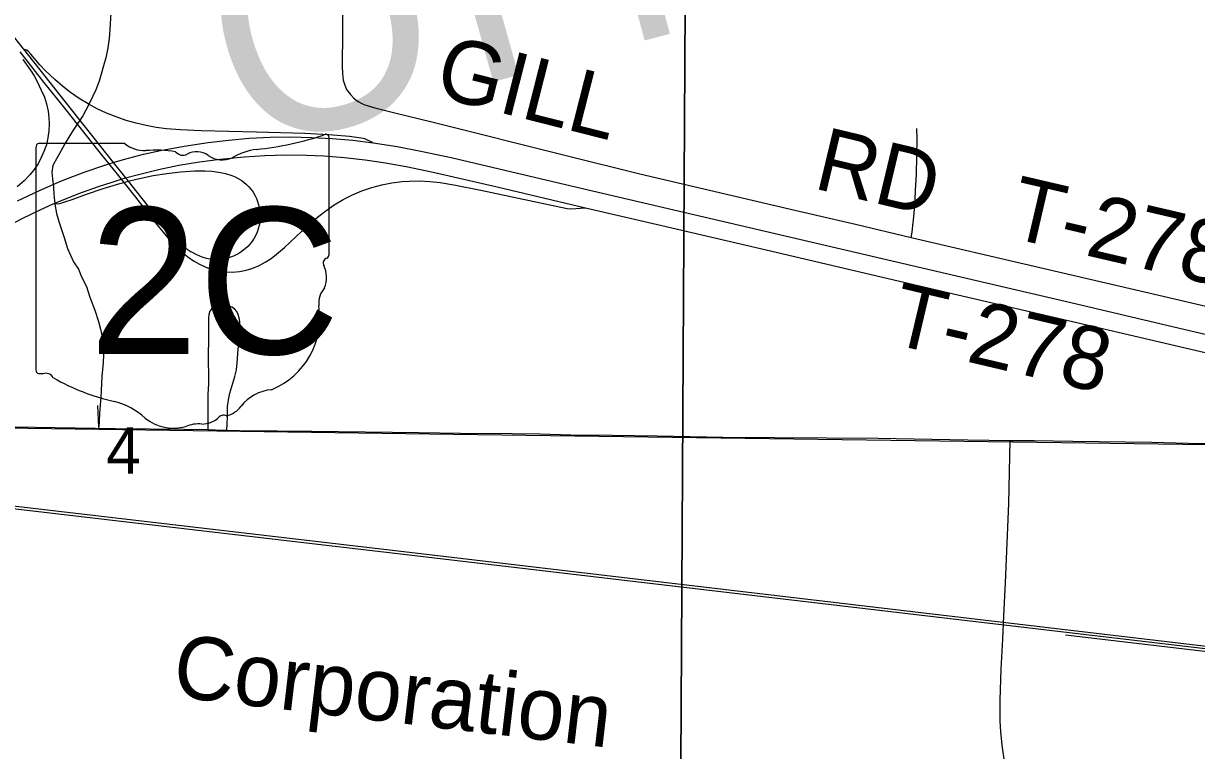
# Model space of a CAD drawing. Extents: x 0 to 34, y 0 to 22.
# Drawn here: x 4.496 to 5.024, y 18.052 to 18.379 of the extents above; entities that cross this region are included whole.
import ezdxf

# ---------------------------------------------------------------- set-up
doc = ezdxf.new("R2010")
doc.units = 0
for name, color, linetype in [('GM_X_Corporation', 7, 'Continuous'), ('GM_X_County_Road', 7, 'Continuous'), ('GM_X_County_Text', 7, 'Continuous'), ('GM_X_Interchange_Ramps', 7, 'Continuous'), ('GM_X_Minor_River', 7, 'Continuous'), ('GM_X_Rail_Line', 7, 'Continuous'), ('GM_X_Rail_Line_Text', 7, 'Continuous'), ('GM_X_Section_Text', 7, 'Continuous'), ('GM_X_State_Location', 7, 'Continuous'), ('GM_X_State_Route', 7, 'Continuous'), ('GM_X_State_Shield', 7, 'Continuous'), ('GM_X_Township_Road', 7, 'Continuous'), ('GM_X_Township_Road_Text', 7, 'Continuous')]:
    doc.layers.add(name, color=color, linetype=linetype)

msp = doc.modelspace()

# ---------------------------------------------------------------- linework, layer by layer
at = {"layer": 'GM_X_Corporation'}
for points in [[(4.7863140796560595, 18.439525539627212), (4.793706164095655, 18.439490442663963), (4.790900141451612, 17.9408439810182), (4.28638989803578, 17.945190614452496), (4.2929909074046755, 18.446469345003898)], [(5.290701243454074, 18.432879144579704), (5.304818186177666, 18.432612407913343), (5.3004127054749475, 17.936980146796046), (5.298641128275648, 17.936856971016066), (4.790900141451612, 17.9408439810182), (4.793706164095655, 18.439490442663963)]]:
    msp.add_lwpolyline(points, close=True, dxfattribs=at)
at = {"layer": 'GM_X_County_Road'}
for points in [[(4.483977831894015, 18.197444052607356), (4.492080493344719, 18.19733221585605), (4.537108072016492, 18.19660519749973), (4.568167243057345, 18.196278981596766), (4.578718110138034, 18.19613296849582)], [(4.578718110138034, 18.19613296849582), (4.58213252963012, 18.196083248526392), (4.587320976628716, 18.195921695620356), (4.592994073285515, 18.19574461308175), (4.610081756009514, 18.195670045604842), (4.625600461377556, 18.195433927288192), (4.673741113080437, 18.19481254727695), (4.692379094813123, 18.194598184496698), (4.715671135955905, 18.194386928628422), (4.72808302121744, 18.1941942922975), (4.742048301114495, 18.193781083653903), (4.760689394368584, 18.19364127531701), (4.780874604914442, 18.19340825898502), (4.810371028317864, 18.19281174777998), (4.880259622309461, 18.192227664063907), (4.920630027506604, 18.191513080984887), (4.939625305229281, 18.191252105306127)], [(4.939625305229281, 18.191252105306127), (4.950396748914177, 18.19122724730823), (4.9679162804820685, 18.190916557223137), (5.00338407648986, 18.19043811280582), (5.025197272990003, 18.189950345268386), (5.040771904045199, 18.189885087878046), (5.046985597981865, 18.19004665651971), (5.053180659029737, 18.190475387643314), (5.0593415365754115, 18.19122102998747), (5.0654527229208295, 18.192305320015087), (5.071504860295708, 18.193694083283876), (5.074114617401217, 18.19440554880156), (5.076320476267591, 18.19516363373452)], [(4.936359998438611, 18.10180434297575), (4.936881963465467, 18.11227598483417), (4.937624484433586, 18.1271671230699), (4.939140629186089, 18.16289587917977), (4.939625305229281, 18.191252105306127)], [(4.946479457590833, 18.005246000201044), (4.944108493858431, 18.01443197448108), (4.941110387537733, 18.026523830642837), (4.938820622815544, 18.037183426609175), (4.9374380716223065, 18.044848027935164), (4.936083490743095, 18.054097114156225), (4.93546213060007, 18.060310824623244), (4.935235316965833, 18.064986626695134), (4.935222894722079, 18.07434133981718), (4.935688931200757, 18.08834080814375), (4.936359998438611, 18.10180434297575)]]:
    msp.add_lwpolyline(points, dxfattribs=at)
at = {"layer": 'GM_X_Interchange_Ramps'}
for points in [[(4.653189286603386, 18.325238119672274), (4.649454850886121, 18.327002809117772), (4.647739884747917, 18.327341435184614), (4.642557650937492, 18.32798145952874), (4.633258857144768, 18.328789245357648), (4.622387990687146, 18.329373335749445), (4.600621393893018, 18.329991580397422), (4.575738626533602, 18.330597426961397), (4.566414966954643, 18.331019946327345), (4.560216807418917, 18.331557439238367), (4.555590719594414, 18.332169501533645), (4.5510018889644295, 18.33298969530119), (4.5464565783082, 18.334036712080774), (4.541973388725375, 18.33531982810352), (4.537564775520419, 18.33684530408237), (4.53324313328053, 18.338600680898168), (4.529014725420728, 18.340573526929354), (4.524891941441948, 18.342760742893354), (4.52089342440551, 18.345165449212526), (4.516969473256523, 18.347918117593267), (4.513346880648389, 18.350763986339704), (4.510016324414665, 18.353755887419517), (4.505719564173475, 18.357667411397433), (4.503255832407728, 18.360320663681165), (4.499101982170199, 18.365102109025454), (4.497890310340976, 18.36639453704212), (4.497268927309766, 18.366935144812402), (4.495833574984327, 18.36737009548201)], [(4.495591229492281, 18.36263215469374), (4.499586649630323, 18.357039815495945), (4.500795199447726, 18.355057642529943), (4.501954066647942, 18.352789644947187), (4.503836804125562, 18.348927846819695), (4.505287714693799, 18.345693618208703), (4.506229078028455, 18.342726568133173), (4.5069654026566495, 18.339479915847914), (4.5073164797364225, 18.33661849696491), (4.507363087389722, 18.333576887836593), (4.507170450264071, 18.33053528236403), (4.506785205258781, 18.32739736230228), (4.506157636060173, 18.324306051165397), (4.505048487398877, 18.321264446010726), (4.503793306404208, 18.31856147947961), (4.502395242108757, 18.31576220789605), (4.5006554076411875, 18.31315246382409), (4.498676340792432, 18.310738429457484), (4.496119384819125, 18.308131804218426), (4.492934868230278, 18.30542882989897)], [(4.509140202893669, 18.297680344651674), (4.512144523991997, 18.2978853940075), (4.514039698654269, 18.298472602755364), (4.517702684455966, 18.299715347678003), (4.524239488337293, 18.30207033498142), (4.5316835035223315, 18.304661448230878), (4.539111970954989, 18.30694497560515), (4.540920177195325, 18.30742965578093), (4.542914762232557, 18.307942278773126), (4.54663366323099, 18.30888675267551), (4.55424233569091, 18.31047124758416), (4.560378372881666, 18.311434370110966), (4.566539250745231, 18.312161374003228), (4.572737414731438, 18.312531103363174), (4.577397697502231, 18.312549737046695), (4.580507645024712, 18.312403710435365), (4.583602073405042, 18.312055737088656), (4.586643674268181, 18.31144680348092), (4.589595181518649, 18.310511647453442), (4.591030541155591, 18.309899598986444), (4.5924131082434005, 18.309206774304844), (4.593736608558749, 18.30839587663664), (4.594994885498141, 18.30749798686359), (4.596172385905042, 18.306491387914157), (4.597262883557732, 18.30539155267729), (4.5982539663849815, 18.304201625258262), (4.599145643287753, 18.302934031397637), (4.599934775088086, 18.30160118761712), (4.600605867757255, 18.300200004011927), (4.601174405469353, 18.298752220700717), (4.601621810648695, 18.297264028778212), (4.601957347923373, 18.295747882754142), (4.602168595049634, 18.294209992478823), (4.602264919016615, 18.292659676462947), (4.602236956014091, 18.29110935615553), (4.6020878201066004, 18.28956215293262), (4.601817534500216, 18.288033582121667), (4.6014291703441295, 18.286532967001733), (4.600910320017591, 18.285069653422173), (4.600288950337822, 18.283646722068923), (4.599546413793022, 18.2822859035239), (4.598707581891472, 18.28098102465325), (4.597769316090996, 18.279744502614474), (4.596725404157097, 18.278594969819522), (4.59560071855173, 18.277526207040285), (4.594389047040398, 18.276556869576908), (4.5931059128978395, 18.275680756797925), (4.591754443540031, 18.274919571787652), (4.590353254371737, 18.274254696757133), (4.588899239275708, 18.27371099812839), (4.587407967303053, 18.273282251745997), (4.585888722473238, 18.272974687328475), (4.584350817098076, 18.272785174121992), (4.582803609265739, 18.272710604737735), (4.581253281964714, 18.272757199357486), (4.579709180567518, 18.272918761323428), (4.578189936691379, 18.273217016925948), (4.576692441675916, 18.27362401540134), (4.575235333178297, 18.274136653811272), (4.573803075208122, 18.274742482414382), (4.571239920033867, 18.276115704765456)]]:
    msp.add_lwpolyline(points, dxfattribs=at)
at = {"layer": 'GM_X_Minor_River'}
msp.add_lwpolyline([(4.535069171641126, 18.383743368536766), (4.534727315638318, 18.3761392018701), (4.534368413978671, 18.37214677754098), (4.5338201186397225, 18.367963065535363), (4.53289492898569, 18.36339867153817), (4.531774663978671, 18.35978124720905), (4.530843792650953, 18.356166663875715), (4.529910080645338, 18.352931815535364), (4.5284119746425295, 18.3491231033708), (4.5269091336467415, 18.345885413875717), (4.525218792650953, 18.342456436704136), (4.522587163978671, 18.337313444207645), (4.520324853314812, 18.334071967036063), (4.518253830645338, 18.330831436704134), (4.516181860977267, 18.32778124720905), (4.51448867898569, 18.3247329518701), (4.512606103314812, 18.321493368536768), (4.510725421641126, 18.31806249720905), (4.509032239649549, 18.3150142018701), (4.508668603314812, 18.311971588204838), (4.508873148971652, 18.308931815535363), (4.509271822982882, 18.305322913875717), (4.509478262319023, 18.302092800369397), (4.50988072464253, 18.297534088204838), (4.51066197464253, 18.29335605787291), (4.511821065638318, 18.28937120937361), (4.512976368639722, 18.28614583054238), (4.514133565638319, 18.282540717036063), (4.515677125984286, 18.277607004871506), (4.518365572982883, 18.271728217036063), (4.520661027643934, 18.26831723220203), (4.522006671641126, 18.26490245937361), (4.5241174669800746, 18.260541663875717), (4.525660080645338, 18.25579734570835), (4.527967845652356, 18.249916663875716), (4.529513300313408, 18.244792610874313), (4.53047920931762, 18.241375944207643), (4.531256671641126, 18.237959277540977), (4.531844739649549, 18.234351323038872), (4.531869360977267, 18.229600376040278), (4.531695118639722, 18.22636931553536), (4.531331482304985, 18.22313636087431), (4.531158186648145, 18.220094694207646), (4.530984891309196, 18.216863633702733), (4.530809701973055, 18.213821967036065), (4.530636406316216, 18.210780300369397), (4.5302756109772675, 18.20697727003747), (4.53010420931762, 18.203366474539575), (4.529930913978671, 18.200134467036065), (4.529756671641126, 18.197092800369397), (4.5293267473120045, 18.20697348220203)], dxfattribs=at)
at = {"layer": 'GM_X_Rail_Line'}
for points in [[(4.40206186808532, 18.198089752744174), (4.689172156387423, 18.194089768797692), (5.00634961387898, 18.189760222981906), (5.158754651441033, 18.18759547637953), (5.362477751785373, 18.182647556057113), (5.718297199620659, 18.179555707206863), (5.931912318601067, 18.177082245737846), (6.251871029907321, 18.271402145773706), (6.499490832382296, 18.346858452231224), (7.043266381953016, 18.517872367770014), (7.079127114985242, 18.527767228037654), (7.128898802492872, 18.529932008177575), (7.241734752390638, 18.536426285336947), (7.289651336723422, 18.563330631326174), (7.338185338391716, 18.597657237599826)], [(4.301188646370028, 18.184044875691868), (4.669435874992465, 18.14102596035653), (5.180445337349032, 18.08076212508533), (5.377502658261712, 18.058353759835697), (5.425517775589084, 18.05195899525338), (5.449742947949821, 18.049302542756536), (5.589237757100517, 18.032723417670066), (5.690295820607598, 18.020904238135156), (5.758989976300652, 18.012773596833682), (5.8874553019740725, 17.99778132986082), (5.939531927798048, 17.991554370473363), (5.980265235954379, 17.98675519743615), (5.999674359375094, 17.984413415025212), (6.017423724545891, 17.981872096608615)], [(4.301053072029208, 18.18289140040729), (4.669299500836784, 18.139872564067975), (5.1803107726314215, 18.079608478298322), (5.377359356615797, 18.05720110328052), (5.42537678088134, 18.050806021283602), (5.449610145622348, 18.048148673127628), (5.589100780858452, 18.03157003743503), (5.690159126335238, 18.019750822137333), (5.758853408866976, 18.01162014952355), (5.887318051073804, 17.996627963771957), (5.9393940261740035, 17.99040107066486), (5.980126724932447, 17.985601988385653), (5.999521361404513, 17.983261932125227), (6.017250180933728, 17.98072357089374)], [(4.964565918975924, 18.10386820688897), (5.1801762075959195, 18.078454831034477), (5.36393862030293, 18.057557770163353)]]:
    msp.add_lwpolyline(points, dxfattribs=at)
at = {"layer": 'GM_X_State_Route'}
for points in [[(4.488529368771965, 18.376684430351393), (4.495143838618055, 18.368236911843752), (4.495833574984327, 18.36737009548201), (4.517301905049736, 18.340225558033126), (4.5362474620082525, 18.316315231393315), (4.541731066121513, 18.309402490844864), (4.542914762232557, 18.307942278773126), (4.552993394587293, 18.295250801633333), (4.560810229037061, 18.285597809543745), (4.563910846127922, 18.28211814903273), (4.566135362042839, 18.27994956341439), (4.5685120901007, 18.277961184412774), (4.571239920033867, 18.276115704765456)], [(4.494267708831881, 18.366105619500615), (4.504899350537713, 18.35250072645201), (4.51421991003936, 18.340818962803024), (4.5298100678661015, 18.3213763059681), (4.531006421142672, 18.31987174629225)], [(4.493158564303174, 18.299103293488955), (4.502997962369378, 18.30372938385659), (4.512961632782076, 18.308075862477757), (4.523096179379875, 18.312012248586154), (4.5319258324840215, 18.315016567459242), (4.534296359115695, 18.315734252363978), (4.5362474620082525, 18.316315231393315), (4.540858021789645, 18.317688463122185), (4.549886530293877, 18.320034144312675), (4.557467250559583, 18.32170563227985), (4.568151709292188, 18.323709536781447), (4.57890139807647, 18.325346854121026), (4.588150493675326, 18.32645288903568), (4.597430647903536, 18.327232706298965), (4.60673566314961, 18.327686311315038), (4.616050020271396, 18.32783544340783), (4.625367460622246, 18.32767699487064), (4.6346693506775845, 18.32721406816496), (4.643946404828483, 18.32639695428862), (4.653189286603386, 18.325238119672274), (4.6639234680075, 18.3235231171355), (4.674607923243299, 18.32149434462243), (4.688278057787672, 18.31853973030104), (4.747339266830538, 18.304723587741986), (4.7973036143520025, 18.292992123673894), (4.886662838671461, 18.272126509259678), (4.96690966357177, 18.253289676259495), (5.018399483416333, 18.2412351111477), (5.056253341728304, 18.232368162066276)], [(4.531006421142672, 18.31987174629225), (4.534296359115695, 18.315734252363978), (4.539758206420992, 18.308852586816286), (4.540920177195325, 18.30742965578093), (4.5462546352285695, 18.300715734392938), (4.555789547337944, 18.28845300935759), (4.560763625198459, 18.28248784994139), (4.563929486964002, 18.279067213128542), (4.5673190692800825, 18.275873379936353), (4.56973619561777, 18.273919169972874), (4.572286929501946, 18.27214515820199), (4.574980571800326, 18.27058240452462), (4.5777953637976, 18.269271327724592), (4.580712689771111, 18.268230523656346), (4.583729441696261, 18.267515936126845), (4.586808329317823, 18.267130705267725), (4.589912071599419, 18.26707476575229), (4.593003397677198, 18.267345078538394), (4.596048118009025, 18.267944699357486), (4.59901824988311, 18.268851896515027), (4.601882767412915, 18.27004181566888), (4.604616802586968, 18.271511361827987), (4.607201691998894, 18.273210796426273), (4.609684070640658, 18.275084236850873), (4.6132227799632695, 18.278128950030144), (4.623419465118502, 18.28771046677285), (4.6281263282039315, 18.29177113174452), (4.631807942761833, 18.294620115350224), (4.63566044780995, 18.297245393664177), (4.639662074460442, 18.299637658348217), (4.643809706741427, 18.301756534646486), (4.648097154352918, 18.30358337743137), (4.652499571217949, 18.30510882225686), (4.656998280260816, 18.30632670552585), (4.661568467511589, 18.307240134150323), (4.6661883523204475, 18.30782110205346), (4.669282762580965, 18.308023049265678), (4.673943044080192, 18.308082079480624), (4.678590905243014, 18.30782111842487), (4.683223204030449, 18.30731468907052), (4.689362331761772, 18.30634535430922), (4.701562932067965, 18.303949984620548), (4.740379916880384, 18.295719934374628), (4.742032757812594, 18.295570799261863), (4.748700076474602, 18.29602440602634)], [(4.535692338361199, 18.307579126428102), (4.538506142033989, 18.30847975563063), (4.539758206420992, 18.308852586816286), (4.541731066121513, 18.309402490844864), (4.54751912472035, 18.311014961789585), (4.556612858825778, 18.313230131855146), (4.565778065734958, 18.315119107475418), (4.574999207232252, 18.316678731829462), (4.584263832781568, 18.31791837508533), (4.595109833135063, 18.318962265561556), (4.604433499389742, 18.31953393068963), (4.613772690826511, 18.31976072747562), (4.623114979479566, 18.319667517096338), (4.6308945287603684, 18.319344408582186), (4.640208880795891, 18.318629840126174), (4.649492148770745, 18.317592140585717), (4.6587350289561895, 18.316256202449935), (4.667928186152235, 18.314603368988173), (4.680103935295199, 18.312027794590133), (4.708882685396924, 18.305372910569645), (4.748700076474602, 18.29602440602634)], [(4.509140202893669, 18.297680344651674), (4.512119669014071, 18.29901009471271), (4.520797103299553, 18.302477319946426), (4.529595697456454, 18.305627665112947), (4.535692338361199, 18.307579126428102)], [(4.444049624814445, 18.257789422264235), (4.450395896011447, 18.26299238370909), (4.459769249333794, 18.269936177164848), (4.470068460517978, 18.276883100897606), (4.477503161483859, 18.281285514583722), (4.48693554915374, 18.286738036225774), (4.495193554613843, 18.29110625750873), (4.503591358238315, 18.295197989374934), (4.509140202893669, 18.297680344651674)], [(4.748700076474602, 18.29602440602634), (4.783021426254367, 18.287965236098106), (4.829962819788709, 18.277097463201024), (4.911641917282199, 18.257803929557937), (4.976733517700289, 18.242654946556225), (5.111306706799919, 18.211222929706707), (5.120518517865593, 18.2090823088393), (5.193144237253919, 18.192028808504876), (5.345995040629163, 18.156290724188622), (5.42624185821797, 18.13749117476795), (5.439800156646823, 18.134315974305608), (5.569924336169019, 18.103903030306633), (5.586632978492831, 18.10032703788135), (5.595785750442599, 18.09861517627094), (5.604985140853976, 18.097186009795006), (5.6157659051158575, 18.09583452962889), (5.6265808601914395, 18.094778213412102), (5.637423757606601, 18.094035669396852), (5.6513859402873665, 18.09349817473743), (5.670474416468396, 18.093072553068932)]]:
    msp.add_lwpolyline(points, dxfattribs=at)
at = {"layer": 'GM_X_State_Shield'}
for p, q in [((4.6332900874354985, 18.275023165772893), (4.6332900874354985, 18.32736586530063)), ((4.501456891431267, 18.32316457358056), (4.501456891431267, 18.223104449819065)), ((4.541362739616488, 18.32488620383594), (4.50275453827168, 18.32488620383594)), ((4.633277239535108, 18.275036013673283), (4.6332900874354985, 18.275023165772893))]:
    msp.add_line(p, q, dxfattribs=at)
for centre, radius, start, end in [((4.5863291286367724, 18.461302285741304), 0.1398078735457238, 275.8444694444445, 288.9064527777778), ((4.631827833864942, 18.327582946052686), 0.0014676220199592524, 351.8620861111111, 97.738), ((4.502967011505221, 18.323377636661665), 0.001527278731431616, 98.1301027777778, 188.13010277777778), ((4.5505572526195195, 18.336502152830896), 0.014813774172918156, 231.61950555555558, 271.11188333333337), ((4.555468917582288, 18.26871131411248), 0.053181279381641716, 80.48669166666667, 94.98826944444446), ((4.567542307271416, 18.323896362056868), 0.00427366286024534, 219.79206111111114, 297.1023694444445), ((4.573816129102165, 18.312331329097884), 0.008885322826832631, 54.466683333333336, 119.14113055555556), ((4.604162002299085, 18.294324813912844), 0.028127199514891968, 97.34618055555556, 120.7688527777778), ((4.585284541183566, 18.328193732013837), 0.010688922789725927, 233.85620555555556, 294.82819166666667), ((4.632951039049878, 18.271180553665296), 0.002271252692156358, 107.94398333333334, 210.33696666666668), ((4.631724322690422, 18.274820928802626), 0.001570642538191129, 289.6038111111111, 7.734130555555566), ((4.618501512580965, 18.26456407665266), 0.013634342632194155, 340.0329638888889, 23.649566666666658), ((4.638548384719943, 18.253118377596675), 0.009919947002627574, 136.80649722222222, 186.92959444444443), ((4.594160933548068, 18.246459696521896), 0.03496914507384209, 292.3088861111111, 8.985838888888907), ((4.502980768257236, 18.222885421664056), 0.0015408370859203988, 171.9583861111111, 258.30661388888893), ((4.503214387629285, 18.233122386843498), 0.011758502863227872, 267.33899444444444, 280.6038555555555), ((4.505620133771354, 18.21733173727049), 0.00423985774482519, 29.748380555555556, 93.27174722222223), ((4.559150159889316, 18.30723159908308), 0.10096071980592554, 240.41292222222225, 257.1985), ((4.6089055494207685, 18.19501278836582), 0.01915169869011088, 94.40312222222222, 142.57675), ((4.529050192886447, 18.178152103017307), 0.031588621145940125, 47.184155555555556, 75.83597222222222), ((4.584640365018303, 18.213406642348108), 0.011297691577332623, 282.8731916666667, 323.27711111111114), ((4.5632151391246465, 18.216835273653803), 0.02004484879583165, 230.70037222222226, 286.29183611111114), ((4.576261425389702, 18.20934206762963), 0.010679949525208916, 268.7770194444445, 315.54927222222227), ((4.585922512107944, 18.199651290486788), 0.0030069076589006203, 65.75173055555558, 132.64842222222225), ((4.574797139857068, 18.182240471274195), 0.016470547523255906, 85.69512222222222, 111.20994722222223)]:
    msp.add_arc(centre, radius, start, end, dxfattribs=at)
at = {"layer": 'GM_X_Township_Road'}
for points in [[(4.639544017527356, 18.390401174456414), (4.639255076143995, 18.359534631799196), (4.639298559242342, 18.35646505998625), (4.63964963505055, 18.353473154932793), (4.640336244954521, 18.35114923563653), (4.6412092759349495, 18.34918880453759), (4.642865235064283, 18.34701091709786), (4.644291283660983, 18.34543262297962), (4.645462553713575, 18.344466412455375), (4.646708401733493, 18.34361511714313), (4.648028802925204, 18.34290986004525), (4.649426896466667, 18.342322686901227), (4.653832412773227, 18.340952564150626), (4.6628826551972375, 18.338706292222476), (4.679547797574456, 18.334682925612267), (4.739920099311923, 18.31948112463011), (4.7731540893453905, 18.3112510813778), (4.842859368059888, 18.294909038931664), (4.870162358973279, 18.2886176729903), (4.8950792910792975, 18.28257796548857)], [(4.8950792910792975, 18.28257796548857), (4.895570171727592, 18.284973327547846), (4.895949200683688, 18.287968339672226), (4.896384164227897, 18.291836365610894), (4.896657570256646, 18.295701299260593), (4.896955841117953, 18.29970912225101), (4.897086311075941, 18.30372005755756), (4.897471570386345, 18.311157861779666), (4.8976641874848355, 18.31924187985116), (4.8978568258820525, 18.32700279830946), (4.897664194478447, 18.331725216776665)], [(4.8950792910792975, 18.28257796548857), (4.950402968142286, 18.26976530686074), (5.006481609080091, 18.25662332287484), (5.04692036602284, 18.24720337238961)], [(4.587320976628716, 18.195921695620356), (4.58744524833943, 18.19871165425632), (4.587581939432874, 18.201818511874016), (4.587678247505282, 18.206497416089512), (4.5880293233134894, 18.20957940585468), (4.588722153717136, 18.2126054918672), (4.590946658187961, 18.22008055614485), (4.591614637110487, 18.22311907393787), (4.591984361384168, 18.226207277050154), (4.5924690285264, 18.23242097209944), (4.592938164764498, 18.237071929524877), (4.5931898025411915, 18.243307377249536), (4.593102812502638, 18.244863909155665), (4.592863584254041, 18.246411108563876), (4.592434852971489, 18.247921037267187), (4.591766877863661, 18.249343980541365), (4.590797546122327, 18.250527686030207), (4.5895050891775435, 18.251301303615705), (4.588026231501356, 18.2517766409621), (4.586475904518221, 18.252071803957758), (4.584906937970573, 18.252171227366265), (4.583359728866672, 18.252015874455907), (4.58187465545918, 18.251521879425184), (4.580603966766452, 18.250648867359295), (4.579712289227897, 18.249418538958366), (4.5792680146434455, 18.247942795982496), (4.579115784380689, 18.24638004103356), (4.57903810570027, 18.24014459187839), (4.579028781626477, 18.235468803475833), (4.578951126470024, 18.230799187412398), (4.578997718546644, 18.216793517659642), (4.57882996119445, 18.21212080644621), (4.578724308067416, 18.205891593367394), (4.578721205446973, 18.19972759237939), (4.578718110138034, 18.19613296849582)]]:
    msp.add_lwpolyline(points, dxfattribs=at)

# ---------------------------------------------------------------- texts
at = {"layer": 'GM_X_County_Text'}
for s, height, rotation, p in [('T', 0.09469696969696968, 14.982348, (4.743590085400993, 18.362770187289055)), ('T', 0.09469696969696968, 15.607727, (4.675632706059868, 18.34378471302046)), ('O', 0.09469696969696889, 17.077944, (4.596191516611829, 18.31937025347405))]:
    msp.add_text(s, height=height, rotation=rotation, dxfattribs=at).set_placement(p)
at = {"layer": 'GM_X_Rail_Line_Text'}
msp.add_text('Corporation', height=0.02831439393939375, rotation=353.28393500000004, dxfattribs=at).set_placement((4.562241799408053, 18.076156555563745))
at = {"layer": 'GM_X_Section_Text'}
msp.add_text('4', height=0.0209280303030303, rotation=1e-05, dxfattribs=at).set_placement((4.533082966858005, 18.176303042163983))
at = {"layer": 'GM_X_State_Location'}
for s, p in [('s', (4.565888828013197, 18.266482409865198)), ('r', (4.565883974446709, 18.266482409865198))]:
    msp.add_text(s, height=9.46969696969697e-05, dxfattribs=at).set_placement(p)
msp.add_text('2C', height=9.46969696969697e-05, rotation=1e-05, dxfattribs=at).set_placement((4.539124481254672, 18.25917565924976))
at = {"layer": 'GM_X_State_Shield'}
msp.add_text('2C', height=0.06591810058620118, dxfattribs=at).set_placement((4.525411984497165, 18.230160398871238))
at = {"layer": 'GM_X_Township_Road_Text'}
for s, height, rotation, p in [('GILL', 0.02840909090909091, 345.744356, (4.679864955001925, 18.34651615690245)), ('RD', 0.02840909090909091, 346.562732, (4.8505795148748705, 18.304872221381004)), ('T-278', 0.028409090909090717, 346.88511900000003, (4.937905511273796, 18.282924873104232)), ('T-278', 0.02840909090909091, 346.710945, (4.884456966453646, 18.235212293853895))]:
    msp.add_text(s, height=height, rotation=rotation, dxfattribs=at).set_placement(p)

doc.saveas('drawing.dxf')
